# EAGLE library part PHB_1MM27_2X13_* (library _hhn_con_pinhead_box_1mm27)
Pin Header Box-Type, 1.27mm/0.5"/50mil Pitch, 2x13 Circuits Note: see library description for an important note about THT-version
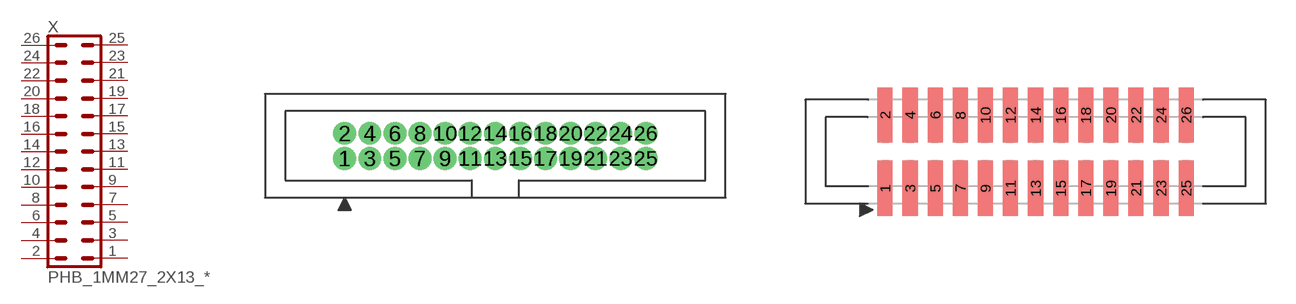
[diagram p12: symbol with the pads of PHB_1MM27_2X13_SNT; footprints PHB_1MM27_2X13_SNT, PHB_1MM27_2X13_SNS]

Designator prefix X

## PHB_1MM27_2X13_SNT  [PHB_1MM27_2X13_SNT]
1  1  pas
2  2  pas
3  3  pas
4  4  pas
5  5  pas
6  6  pas
7  7  pas
8  8  pas
9  9  pas
10  10  pas
11  11  pas
12  12  pas
13  13  pas
14  14  pas
15  15  pas
16  16  pas
17  17  pas
18  18  pas
19  19  pas
20  20  pas
21  21  pas
22  22  pas
23  23  pas
24  24  pas
25  25  pas
26  26  pas

## PHB_1MM27_2X13_SNS  [PHB_1MM27_2X13_SNS]
Pads as for PHB_1MM27_2X13_SNT

## Footprint PHB_1MM27_2X13_SNT (pad centres in mm)
Pin Header Box-Type, 1.27mm Pitch, 2x13 circuits, Straight, No Locking, THT Important Note: Diameter in this lbr is set to a specific value (NOT 'auto' = 0), this is ignored by actual eagle versions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
drill 0.65 pad 1 round: 1 -7.62,-0.635; 2 -7.62,0.635; 3 -6.35,-0.635; 4 -6.35,0.635; 5 -5.08,-0.635; 6 -5.08,0.635; 7 -3.81,-0.635; 8 -3.81,0.635; 9 -2.54,-0.635; 10 -2.54,0.635; 11 -1.27,-0.635; 12 -1.27,0.635; 13 0,-0.635; 14 0,0.635; 15 1.27,-0.635; 16 1.27,0.635; 17 2.54,-0.635; 18 2.54,0.635; 19 3.81,-0.635; 20 3.81,0.635; 21 5.08,-0.635; 22 5.08,0.635; 23 6.35,-0.635; 24 6.35,0.635; 25 7.62,-0.635; 26 7.62,0.635

## Footprint PHB_1MM27_2X13_SNS (pad centres in mm)
Pin Header Box-Type, 1.27mm Pitch, 2x13 circuits, Straight, No Locking, SMT
smd 0.76 x 2.8: 1 -7.62,-1.85; 2 -7.62,1.85; 3 -6.35,-1.85; 4 -6.35,1.85; 5 -5.08,-1.85; 6 -5.08,1.85; 7 -3.81,-1.85; 8 -3.81,1.85; 9 -2.54,-1.85; 10 -2.54,1.85; 11 -1.27,-1.85; 12 -1.27,1.85; 13 0,-1.85; 14 0,1.85; 15 1.27,-1.85; 16 1.27,1.85; 17 2.54,-1.85; 18 2.54,1.85; 19 3.81,-1.85; 20 3.81,1.85; 21 5.08,-1.85; 22 5.08,1.85; 23 6.35,-1.85; 24 6.35,1.85; 25 7.62,-1.85; 26 7.62,1.85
